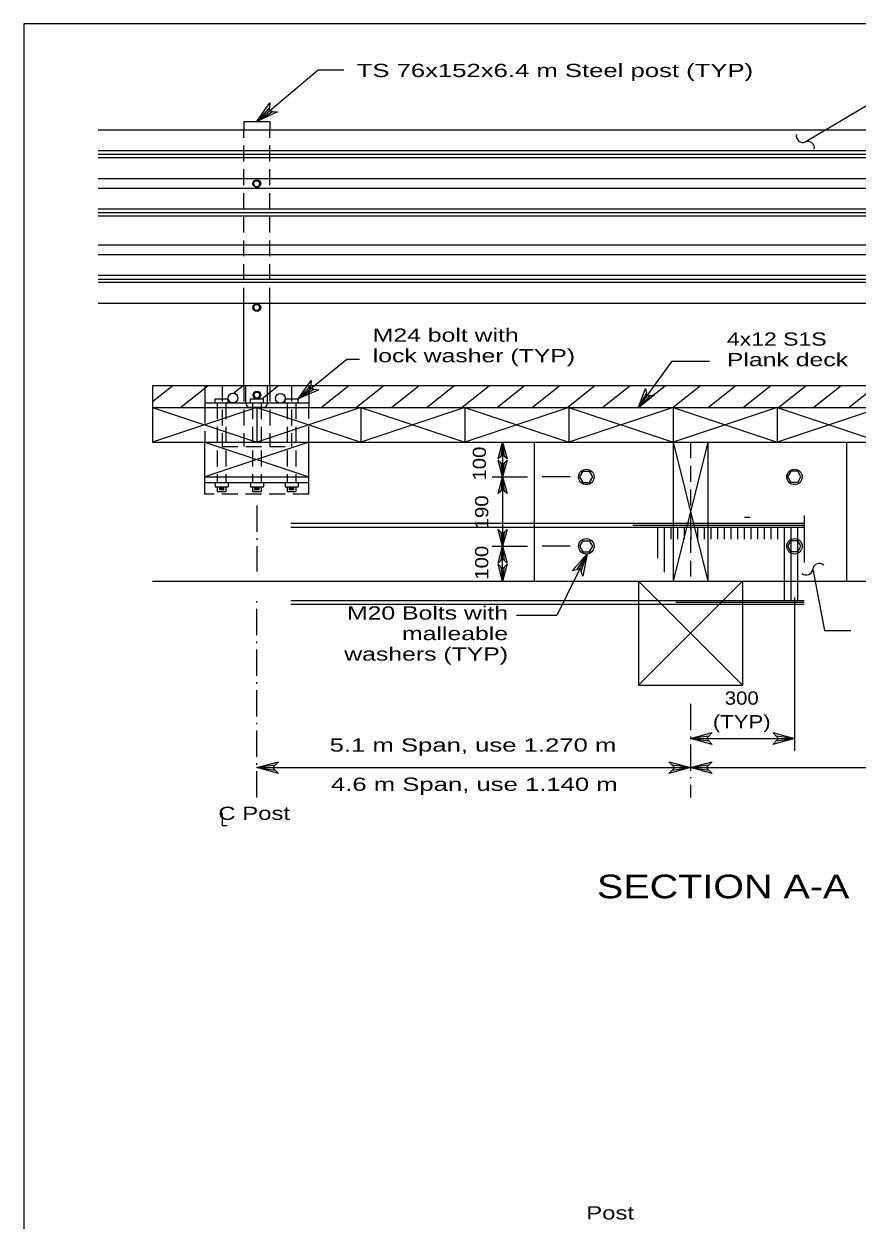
# Model space of a CAD drawing. Extents: x 13426 to 15509, y -9298 to -5111.
# Drawn here: x 15181.1 to 15263.4, y -5229.2 to -5111 of the extents above; entities that cross this region are included whole.
import ezdxf
from ezdxf.enums import TextEntityAlignment as Align

# ---------------------------------------------------------------- set-up
doc = ezdxf.new("R2010")
doc.units = 0
doc.header["$LTSCALE"] = 0.52
doc.linetypes.add('DOT_DASHED', pattern=[7.7, 5, -1.2, 0.3, -1.2])
doc.linetypes.add('MEDIUM_DASHED', pattern=[4.5, 3, -1.5])
for name, color, linetype, lineweight in [('1', 7, 'Continuous', 13), ('11', 7, 'Continuous', 13), ('15', 7, 'Continuous', 13), ('16', 7, 'Continuous', 25), ('2', 7, 'Continuous', 25), ('20', 7, 'Continuous', 13), ('30', 7, 'Continuous', 25), ('4', 7, 'Continuous', 13), ('5', 7, 'Continuous', 25)]:
    doc.layers.add(name, color=color, linetype=linetype, lineweight=lineweight)
doc.layers.add('19', color=7, linetype='Continuous')

msp = doc.modelspace()

# ---------------------------------------------------------------- linework, layer by layer
at = {"layer": '1', "lineweight": 25}
for p, q in [((15303.296, -5121.538), (15188.44, -5121.538)), ((15303.296, -5126.334), (15188.44, -5126.334)), ((15303.296, -5127.298), (15188.44, -5127.298)), ((15203.806, -5126.809), (15203.964, -5126.535)), ((15203.964, -5127.091), (15203.806, -5126.809)), ((15203.964, -5126.535), (15204.286, -5126.535)), ((15203.964, -5127.091), (15204.281, -5127.091)), ((15204.281, -5127.091), (15204.444, -5126.813)), ((15204.444, -5126.813), (15204.286, -5126.535)), ((15303.296, -5132.898), (15188.44, -5132.898)), ((15303.296, -5133.864), (15188.44, -5133.864)), ((15303.296, -5138.664), (15188.44, -5138.664)), ((15203.806, -5139.043), (15203.964, -5138.769)), ((15203.964, -5139.326), (15203.806, -5139.043)), ((15203.964, -5138.769), (15204.286, -5138.769)), ((15204.281, -5139.326), (15204.444, -5139.047)), ((15204.444, -5139.047), (15204.286, -5138.769)), ((15203.964, -5139.326), (15204.281, -5139.326)), ((15284.634, -5146.793), (15193.834, -5146.793)), ((15198.973, -5146.793), (15198.973, -5148.935)), ((15203.042, -5148.507), (15203.042, -5146.793)), ((15203.819, -5147.691), (15203.977, -5147.416)), ((15203.977, -5147.416), (15204.299, -5147.416)), ((15204.457, -5147.695), (15204.299, -5147.416)), ((15205.183, -5148.507), (15205.183, -5146.793)), ((15209.253, -5146.793), (15209.253, -5148.935)), ((15209.253, -5148.507), (15198.973, -5148.507)), ((15203.977, -5147.973), (15203.819, -5147.691)), ((15203.977, -5147.973), (15204.295, -5147.973)), ((15204.295, -5147.973), (15204.457, -5147.695)), ((15204.755, -5148.935), (15203.47, -5148.935)), ((15198.973, -5156.323), (15198.973, -5152.362)), ((15209.253, -5156.323), (15209.253, -5152.362))]:
    msp.add_line(p, q, dxfattribs=at)
at = {"layer": '1'}
for p, q in [((15303.296, -5123.566), (15188.44, -5123.566)), ((15303.296, -5123.949), (15188.44, -5123.949)), ((15303.296, -5124.268), (15188.44, -5124.268)), ((15303.296, -5129.326), (15188.44, -5129.326)), ((15303.296, -5129.709), (15188.44, -5129.709)), ((15303.296, -5130.028), (15188.44, -5130.028)), ((15303.296, -5135.893), (15188.44, -5135.893)), ((15303.296, -5136.276), (15188.44, -5136.276)), ((15303.296, -5136.595), (15188.44, -5136.595)), ((15236.03, -5155.78), (15236.348, -5155.232)), ((15236.348, -5155.232), (15236.99, -5155.232)), ((15237.307, -5155.788), (15236.99, -5155.232)), ((15256.581, -5155.788), (15256.898, -5155.232)), ((15257.54, -5155.232), (15256.898, -5155.232)), ((15257.857, -5155.78), (15257.54, -5155.232)), ((15236.348, -5156.345), (15236.03, -5155.78)), ((15236.348, -5156.345), (15236.982, -5156.345)), ((15236.982, -5156.345), (15237.307, -5155.788)), ((15256.906, -5156.345), (15256.581, -5155.788)), ((15257.54, -5156.345), (15256.906, -5156.345)), ((15257.54, -5156.345), (15257.857, -5155.78)), ((15258.171, -5160.386), (15207.473, -5160.386)), ((15252.849, -5159.806), (15252.3, -5159.806)), ((15258.171, -5159.609), (15258.171, -5164.238)), ((15258.171, -5160.77), (15207.473, -5160.77)), ((15258.171, -5160.578), (15241.261, -5160.578)), ((15236.03, -5162.633), (15236.348, -5162.085)), ((15236.348, -5163.198), (15236.03, -5162.633)), ((15236.348, -5162.085), (15236.99, -5162.085)), ((15236.982, -5163.198), (15237.307, -5162.641)), ((15237.307, -5162.641), (15236.99, -5162.085)), ((15256.581, -5162.641), (15256.898, -5162.085)), ((15256.906, -5163.198), (15256.581, -5162.641)), ((15257.54, -5162.085), (15256.898, -5162.085)), ((15257.857, -5162.633), (15257.54, -5162.085)), ((15257.54, -5163.198), (15257.857, -5162.633)), ((15236.348, -5163.198), (15236.982, -5163.198)), ((15257.54, -5163.198), (15256.906, -5163.198)), ((15258.171, -5168.012), (15207.473, -5168.012)), ((15258.171, -5168.396), (15207.473, -5168.396)), ((15258.171, -5168.204), (15245.492, -5168.204))]:
    msp.add_line(p, q, dxfattribs=at)
at = {"layer": '1', "linetype": 'MEDIUM_DASHED', "lineweight": 25}
for p, q in [((15198.973, -5148.935), (15198.973, -5152.362)), ((15209.253, -5152.362), (15209.253, -5148.935)), ((15209.253, -5157.501), (15209.253, -5156.323))]:
    msp.add_line(p, q, dxfattribs=at)
msp.add_lwpolyline([(15209.253, -5157.501), (15198.973, -5157.501), (15198.973, -5156.323)], dxfattribs=at)
at = {"layer": '1', "lineweight": 25}
for centre in [(15201.7571, -5147.9974), (15206.448, -5148.0187)]:
    msp.add_circle(centre, 0.4819, dxfattribs=at)
for centre, start, end in [((15203.4703, -5148.5067), 180, 269.99999), ((15204.7552, -5148.5067), 270, 359.99999)]:
    msp.add_arc(centre, 0.4283, start, end, dxfattribs=at)
at = {"layer": '11'}
for p, q in [((15243.686, -5160.77), (15243.686, -5163.813)), ((15244.344, -5160.77), (15244.344, -5165.196)), ((15245.002, -5160.77), (15245.002, -5161.925)), ((15245.661, -5160.77), (15245.661, -5161.925)), ((15246.32, -5160.77), (15246.32, -5161.925)), ((15246.978, -5160.77), (15246.978, -5161.925)), ((15247.636, -5160.77), (15247.636, -5161.925)), ((15248.294, -5160.77), (15248.294, -5161.925)), ((15248.953, -5160.77), (15248.953, -5161.925)), ((15249.612, -5160.77), (15249.612, -5161.925)), ((15250.27, -5160.77), (15250.27, -5161.925)), ((15250.928, -5160.77), (15250.928, -5161.925)), ((15251.587, -5160.77), (15251.587, -5161.925)), ((15252.245, -5160.77), (15252.245, -5161.925)), ((15252.904, -5160.77), (15252.904, -5161.925)), ((15253.562, -5160.77), (15253.562, -5161.925)), ((15254.22, -5160.77), (15254.22, -5161.925)), ((15254.879, -5160.77), (15254.879, -5161.925)), ((15255.537, -5160.77), (15255.537, -5161.925)), ((15256.195, -5160.77), (15256.195, -5168.012)), ((15256.854, -5160.77), (15256.854, -5168.012)), ((15257.513, -5160.77), (15257.513, -5168.012))]:
    msp.add_line(p, q, dxfattribs=at)
at = {"layer": '15'}
for p, q in [((15228.39, -5152.362), (15228.39, -5155.788)), ((15227.376, -5155.788), (15230.855, -5155.788)), ((15228.39, -5155.788), (15228.39, -5162.641)), ((15228.39, -5166.068), (15228.39, -5162.641))]:
    msp.add_line(p, q, dxfattribs=at)
for points in [[(15204.134, -5120.673), (15210.189, -5115.587), (15212.718, -5115.587)], [(15258.277, -5122.691), (15268.79, -5116.467), (15272.079, -5116.467)], [(15208.205, -5148.078), (15213.007, -5144.145), (15214.253, -5144.145)], [(15241.789, -5148.988), (15245.152, -5144.343), (15248.825, -5144.343)], [(15236.757, -5163.398), (15233.745, -5169.471), (15229.784, -5169.471)], [(15259.03, -5164.885), (15260.196, -5170.954), (15262.783, -5170.954)]]:
    msp.add_lwpolyline(points, dxfattribs=at)
for centre, start, end in [((15258.0463, -5122.1136), 166.31833, 291.78907), ((15258.5498, -5123.3022), 348.65226, 114.123), ((15258.3873, -5164.8237), 229.05703, 354.52776), ((15259.6694, -5164.973), 46.72309, 172.19383)]:
    msp.add_arc(centre, 0.6455, start, end, dxfattribs=at)
at = {"layer": '16'}
for points in [[(15205.671, -5119.69), (15206.151, -5119.741), (15204.134, -5120.673), (15205.399, -5118.846), (15205.367, -5119.328), (15204.134, -5120.673), (15205.671, -5119.69), (15205.338, -5119.661), (15205.367, -5119.328)], [(15209.755, -5147.115), (15210.234, -5147.172), (15208.205, -5148.078), (15209.493, -5146.267), (15209.455, -5146.748), (15208.205, -5148.078), (15209.755, -5147.115), (15209.422, -5147.081), (15209.455, -5146.748)], [(15242.957, -5147.75), (15243.402, -5147.688), (15241.789, -5148.988), (15242.52, -5147.049), (15242.6, -5147.491), (15241.789, -5148.988), (15242.957, -5147.75), (15242.649, -5147.8), (15242.6, -5147.491)], [(15228.208, -5153.754), (15227.941, -5154.011), (15228.39, -5152.362), (15228.84, -5154.011), (15228.573, -5153.754), (15228.39, -5152.362), (15228.208, -5153.754), (15228.39, -5153.572), (15228.573, -5153.754)], [(15228.573, -5154.396), (15228.84, -5154.139), (15228.39, -5155.788), (15227.941, -5154.139), (15228.208, -5154.396), (15228.39, -5155.788), (15228.573, -5154.396), (15228.39, -5154.578), (15228.208, -5154.396)], [(15228.208, -5157.18), (15227.941, -5157.437), (15228.39, -5155.788), (15228.84, -5157.437), (15228.573, -5157.18), (15228.39, -5155.788), (15228.208, -5157.18), (15228.39, -5156.998), (15228.573, -5157.18)], [(15228.573, -5161.249), (15228.84, -5160.992), (15228.39, -5162.641), (15227.941, -5160.992), (15228.208, -5161.249), (15228.39, -5162.641), (15228.573, -5161.249), (15228.39, -5161.431), (15228.208, -5161.249)], [(15228.208, -5164.033), (15227.941, -5164.29), (15228.39, -5162.641), (15228.84, -5164.29), (15228.573, -5164.033), (15228.39, -5162.641), (15228.208, -5164.033), (15228.39, -5163.851), (15228.573, -5164.033)], [(15235.741, -5164.914), (15235.28, -5165.059), (15236.757, -5163.398), (15236.328, -5165.578), (15236.165, -5165.125), (15236.757, -5163.398), (15235.741, -5164.914), (15236.058, -5164.807), (15236.165, -5165.125)], [(15228.573, -5164.676), (15228.84, -5164.419), (15228.39, -5166.068), (15227.941, -5164.419), (15228.208, -5164.676), (15228.39, -5166.068), (15228.573, -5164.676), (15228.39, -5164.858), (15228.208, -5164.676)], [(15248.754, -5181.857), (15249.088, -5182.205), (15246.944, -5181.62), (15249.088, -5181.035), (15248.754, -5181.383), (15246.944, -5181.62), (15248.754, -5181.857), (15248.517, -5181.62), (15248.754, -5181.383)], [(15255.414, -5181.383), (15255.08, -5181.035), (15257.224, -5181.62), (15255.08, -5182.205), (15255.414, -5181.857), (15257.224, -5181.62), (15255.414, -5181.383), (15255.65, -5181.62), (15255.414, -5181.857)], [(15205.923, -5184.734), (15206.257, -5185.082), (15204.113, -5184.497), (15206.257, -5183.913), (15205.923, -5184.261), (15204.113, -5184.497), (15205.923, -5184.734), (15205.686, -5184.497), (15205.923, -5184.261)], [(15245.134, -5184.261), (15244.8, -5183.913), (15246.944, -5184.497), (15244.8, -5185.082), (15245.134, -5184.734), (15246.944, -5184.497), (15245.134, -5184.261), (15245.371, -5184.497), (15245.134, -5184.734)], [(15248.754, -5184.734), (15249.088, -5185.082), (15246.944, -5184.497), (15249.088, -5183.913), (15248.754, -5184.261), (15246.944, -5184.497), (15248.754, -5184.734), (15248.517, -5184.497), (15248.754, -5184.261)]]:
    msp.add_lwpolyline(points, dxfattribs=at)
at = {"layer": '2'}
for centre in [(15204.1227, -5126.8131), (15204.1227, -5139.0472), (15204.1359, -5147.6947)]:
    msp.add_circle(centre, 0.3814, dxfattribs=at)
at = {"layer": '2', "lineweight": 13}
for centre in [(15236.6646, -5155.7882), (15257.2233, -5155.7882), (15236.6646, -5162.6411), (15257.2233, -5162.6411)]:
    msp.add_circle(centre, 0.7627, dxfattribs=at)
at = {"layer": '30'}
for p, q in [((15509.151, -5111.044), (15181.119, -5111.044)), ((15181.119, -5111.081), (15181.119, -5323.3))]:
    msp.add_line(p, q, dxfattribs=at)
at = {"layer": '4', "lineweight": 25}
for p, q in [((15193.834, -5146.793), (15193.834, -5152.362)), ((15195.825, -5146.793), (15193.834, -5148.378)), ((15199.3, -5146.793), (15196.608, -5148.935)), ((15202.774, -5146.793), (15201.854, -5147.525)), ((15206.249, -5146.793), (15204.634, -5148.078)), ((15213.198, -5146.793), (15210.506, -5148.935)), ((15216.673, -5146.793), (15213.98, -5148.935)), ((15220.147, -5146.793), (15217.455, -5148.935)), ((15223.621, -5146.793), (15220.929, -5148.935)), ((15227.096, -5146.793), (15224.404, -5148.935)), ((15230.571, -5146.793), (15227.879, -5148.935)), ((15234.045, -5146.793), (15231.353, -5148.935)), ((15237.52, -5146.793), (15234.828, -5148.935)), ((15240.995, -5146.793), (15238.302, -5148.935)), ((15244.469, -5146.793), (15241.894, -5148.842)), ((15247.944, -5146.793), (15245.251, -5148.935)), ((15251.418, -5146.793), (15248.726, -5148.935)), ((15254.893, -5146.793), (15252.201, -5148.935)), ((15258.367, -5146.793), (15255.675, -5148.935)), ((15261.842, -5146.793), (15259.15, -5148.935)), ((15265.317, -5146.793), (15262.624, -5148.935)), ((15193.834, -5148.935), (15306.907, -5148.935)), ((15193.834, -5148.935), (15204.113, -5152.362)), ((15204.113, -5148.935), (15193.834, -5152.362)), ((15204.113, -5148.935), (15204.113, -5152.362)), ((15204.113, -5148.935), (15214.393, -5152.362)), ((15214.393, -5148.935), (15204.113, -5152.362)), ((15214.393, -5148.935), (15214.393, -5152.362)), ((15214.393, -5148.935), (15224.672, -5152.362)), ((15224.672, -5148.935), (15214.393, -5152.362)), ((15224.672, -5148.935), (15224.672, -5152.362)), ((15224.672, -5148.935), (15234.951, -5152.362)), ((15234.951, -5148.935), (15224.672, -5152.362)), ((15234.951, -5148.935), (15234.951, -5152.362)), ((15234.951, -5148.935), (15245.231, -5152.362)), ((15245.231, -5148.935), (15234.951, -5152.362)), ((15245.231, -5148.935), (15245.231, -5152.362)), ((15245.231, -5148.935), (15255.51, -5152.362)), ((15255.51, -5148.935), (15245.231, -5152.362)), ((15255.51, -5148.935), (15255.51, -5152.362)), ((15255.51, -5148.935), (15265.789, -5152.362)), ((15265.789, -5148.935), (15255.51, -5152.362)), ((15193.834, -5152.362), (15306.907, -5152.362)), ((15198.973, -5152.362), (15209.253, -5155.788)), ((15209.253, -5152.362), (15198.973, -5155.788)), ((15231.525, -5152.362), (15231.525, -5166.068)), ((15245.231, -5152.362), (15245.231, -5166.068)), ((15245.231, -5152.362), (15248.657, -5166.068)), ((15248.657, -5152.362), (15245.231, -5166.068)), ((15248.657, -5152.362), (15248.657, -5166.068)), ((15262.363, -5152.362), (15262.363, -5166.068)), ((15198.973, -5155.788), (15209.253, -5155.788)), ((15198.973, -5156.323), (15209.253, -5156.323)), ((15193.834, -5166.068), (15306.907, -5166.068)), ((15241.804, -5166.068), (15241.804, -5176.347)), ((15252.083, -5166.068), (15241.804, -5176.347)), ((15241.804, -5166.068), (15252.083, -5176.347)), ((15252.083, -5166.068), (15252.083, -5176.347)), ((15241.804, -5176.347), (15252.083, -5176.347))]:
    msp.add_line(p, q, dxfattribs=at)
at = {"layer": '4', "linetype": 'MEDIUM_DASHED', "lineweight": 25}
msp.add_line((15246.944, -5152.362), (15246.944, -5166.068), dxfattribs=at)
at = {"layer": '4'}
for p, q in [((15235.058, -5155.788), (15232.304, -5155.788)), ((15227.376, -5162.641), (15230.855, -5162.641)), ((15235.058, -5162.641), (15232.304, -5162.641)), ((15257.224, -5167.688), (15257.224, -5182.832)), ((15246.944, -5181.62), (15257.224, -5181.62)), ((15204.113, -5184.497), (15246.944, -5184.497)), ((15246.944, -5184.497), (15289.775, -5184.497))]:
    msp.add_line(p, q, dxfattribs=at)
at = {"layer": '4', "linetype": 'DOT_DASHED'}
for p, q in [((15204.113, -5158.616), (15204.113, -5165.118)), ((15204.113, -5187.443), (15204.113, -5167.688)), ((15246.944, -5178.202), (15246.944, -5187.443))]:
    msp.add_line(p, q, dxfattribs=at)
at = {"layer": '5'}
for p, q in [((15202.828, -5120.681), (15205.398, -5120.681)), ((15202.828, -5120.681), (15202.828, -5121.538)), ((15205.398, -5120.681), (15205.398, -5121.538)), ((15202.828, -5146.793), (15202.828, -5138.664)), ((15205.398, -5146.793), (15205.398, -5138.664)), ((15200.011, -5148.506), (15200.011, -5148.078)), ((15200.011, -5148.078), (15201.295, -5148.078)), ((15201.295, -5148.506), (15201.295, -5148.078)), ((15203.494, -5148.506), (15203.494, -5148.078)), ((15203.494, -5148.078), (15204.779, -5148.078)), ((15204.779, -5148.506), (15204.779, -5148.078)), ((15206.92, -5148.506), (15206.92, -5148.078)), ((15206.92, -5148.078), (15208.205, -5148.078)), ((15208.205, -5148.506), (15208.205, -5148.078)), ((15200.01, -5156.324), (15200.01, -5156.753)), ((15200.01, -5156.753), (15201.295, -5156.753)), ((15200.211, -5156.753), (15200.211, -5157.224)), ((15200.388, -5156.903), (15200.888, -5156.903)), ((15201.068, -5156.753), (15201.068, -5157.224)), ((15201.295, -5156.324), (15201.295, -5156.753)), ((15203.494, -5156.324), (15203.494, -5156.753)), ((15203.494, -5156.753), (15204.778, -5156.753)), ((15203.694, -5156.753), (15203.694, -5157.224)), ((15203.871, -5156.904), (15204.371, -5156.904)), ((15204.551, -5156.753), (15204.551, -5157.224)), ((15204.778, -5156.324), (15204.778, -5156.753)), ((15206.92, -5156.324), (15206.92, -5156.753)), ((15206.92, -5156.753), (15208.205, -5156.753)), ((15207.12, -5156.753), (15207.12, -5157.224)), ((15207.298, -5156.903), (15207.797, -5156.903)), ((15207.977, -5156.753), (15207.977, -5157.224)), ((15208.205, -5156.324), (15208.205, -5156.753)), ((15200.211, -5157.224), (15201.068, -5157.224)), ((15200.388, -5157.037), (15200.888, -5157.037)), ((15203.694, -5157.224), (15204.551, -5157.224)), ((15203.871, -5157.037), (15204.371, -5157.037)), ((15207.12, -5157.224), (15207.977, -5157.224)), ((15207.298, -5157.037), (15207.797, -5157.037))]:
    msp.add_line(p, q, dxfattribs=at)
at = {"layer": '5', "linetype": 'MEDIUM_DASHED'}
for p, q in [((15202.828, -5138.664), (15202.828, -5121.538)), ((15205.398, -5138.664), (15205.398, -5121.538)), ((15200.686, -5146.793), (15200.686, -5152.79)), ((15202.828, -5146.793), (15202.828, -5152.79)), ((15205.398, -5146.793), (15205.398, -5152.79)), ((15207.539, -5146.793), (15207.539, -5152.79)), ((15200.211, -5148.507), (15200.211, -5156.323)), ((15201.068, -5148.507), (15201.068, -5156.323)), ((15203.694, -5148.506), (15203.694, -5156.323)), ((15204.551, -5148.506), (15204.551, -5156.323)), ((15207.12, -5148.507), (15207.12, -5156.323)), ((15207.977, -5148.507), (15207.977, -5156.323)), ((15200.686, -5152.79), (15207.539, -5152.79))]:
    msp.add_line(p, q, dxfattribs=at)

# ---------------------------------------------------------------- texts
at = {"layer": '19'}
for s, width, p in [('TS 76x152x6.4 m Steel post (TYP)', 1.45, (15213.982, -5116.293)), ('M24 bolt with', 1.4, (15215.568, -5142.435)), ('lock washer (TYP)', 1.4, (15215.568, -5144.463))]:
    msp.add_text(s, height=1.307, dxfattribs=dict(at, width=width)).set_placement(p)
at = {"layer": '19', "width": 1.15}
for s, p in [('100', (15226.753, -5154.473)), ('190', (15226.983, -5159.286)), ('100', (15226.981, -5164.264))]:
    msp.add_text(s, height=1.307, rotation=90, dxfattribs=at).set_placement(p, align=Align.CENTER)
at = {"layer": '19', "width": 1.4}
for s, p in [('M20 Bolts with', (15228.936, -5169.876)), ('malleable', (15228.936, -5171.904)), ('washers (TYP)', (15228.936, -5173.932))]:
    msp.add_text(s, height=1.307, dxfattribs=at).set_placement(p, align=Align.RIGHT)
at = {"layer": '19'}
for s, width, p in [('300', 1.15, (15252.0135, -5178.282)), ('(TYP)', 1.25, (15252.0135, -5180.619)), ('5.1 m Span, use 1.270 m', 1.45, (15225.4705, -5182.919)), ('4.6 m Span, use 1.140 m', 1.45, (15225.6015, -5186.794))]:
    msp.add_text(s, height=1.307, dxfattribs=dict(at, width=width)).set_placement(p, align=Align.CENTER)
at = {"layer": '20'}
for s, width, p in [('4x12 S1S', 1.3, (15250.546, -5142.823)), ('Plank deck', 1.4, (15250.546, -5144.851))]:
    msp.add_text(s, height=1.307, dxfattribs=dict(at, width=width)).set_placement(p)
for s, height, width, p in [('C Post', 1.307, 1.35, (15203.86, -5189.662)), ('L', 1.307, 0.75, (15200.903, -5190.301)), ('SECTION A-A', 2.333, 1.25, (15250.1765, -5197.403)), ('Post', 1.307, 1.35, (15239.016, -5229.126))]:
    msp.add_text(s, height=height, dxfattribs=dict(at, width=width)).set_placement(p, align=Align.CENTER)

doc.saveas('drawing.dxf')
